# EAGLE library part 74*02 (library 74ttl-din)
Quad 2-input NOR gate
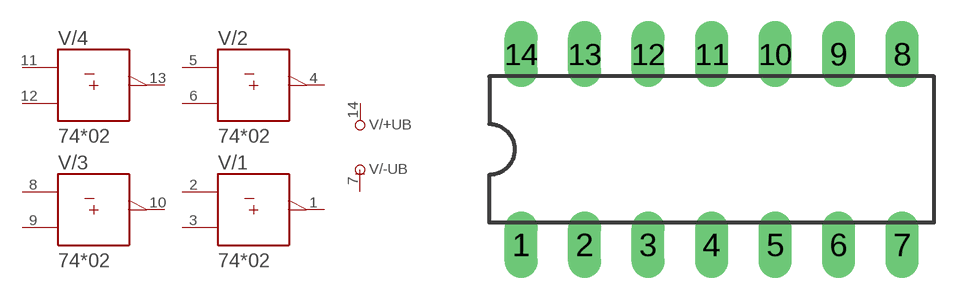
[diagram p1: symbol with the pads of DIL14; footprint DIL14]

Designator prefix V; gates /+UB=+UB /-UB=-UB /1=02 /2=02 /3=02 /4=02

## 7402N  [DIL14]
1  /1:Y  out
2  /1:A  in
3  /1:B  in
4  /2:Y  out
5  /2:A  in
6  /2:B  in
7  /-UB:-UB  pwr
8  /3:A  in
9  /3:B  in
10  /3:Y  out
11  /4:A  in
12  /4:B  in
13  /4:Y  out
14  /+UB:+UB  pwr

## Footprint DIL14 (pad centres in mm)
Dual In Line Package
drill 0.813 long: 1 -7.62,-3.81; 2 -5.08,-3.81; 3 -2.54,-3.81; 4 0,-3.81; 5 2.54,-3.81; 6 5.08,-3.81; 7 7.62,-3.81; 8 7.62,3.81; 9 5.08,3.81; 10 2.54,3.81; 11 0,3.81; 12 -2.54,3.81; 13 -5.08,3.81; 14 -7.62,3.81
